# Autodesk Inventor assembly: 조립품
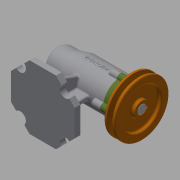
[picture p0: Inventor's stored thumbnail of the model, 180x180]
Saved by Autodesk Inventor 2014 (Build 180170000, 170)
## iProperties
Created: 2019-12
Part Number: 조립품
Document SubType Name: Assembly
Designer: kh
Author: kh
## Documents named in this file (12)
- C:\Users\kh\Desktop\491204V1041\조립품.iam
- C:\Users\kh\Desktop\491204V1041\본체.ipt
- C:\Users\kh\Desktop\491204V1041\V벨트풀리.ipt
- C:\Users\kh\Desktop\491204V1041\멈춤나사 M3.ipt
- C:\Users\kh\Desktop\491204V1041\베어링 6004.ipt
- C:\Users\kh\Desktop\491204V1041\베어링 51202.ipt
- C:\Users\kh\Desktop\491204V1041\볼트 M4.ipt
- C:\Users\kh\Desktop\491204V1041\어댑터슬리브.ipt
- C:\Users\kh\Desktop\491204V1041\오일 실.ipt
- C:\Users\kh\Desktop\491204V1041\축.ipt
- C:\Users\kh\Desktop\491204V1041\커버.ipt
- C:\Users\kh\Desktop\491204V1041\키 5 x 5 x 16.ipt
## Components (1 placed, 1 different names)
1. V벨트풀리:1 — Mate:15, Flush:1, Angle:2
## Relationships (3: Mate 1, Flush 1, Angle 1)
- Mate:15: V벨트풀리:1
- Flush:1: V벨트풀리:1
- Angle:2: V벨트풀리:1
